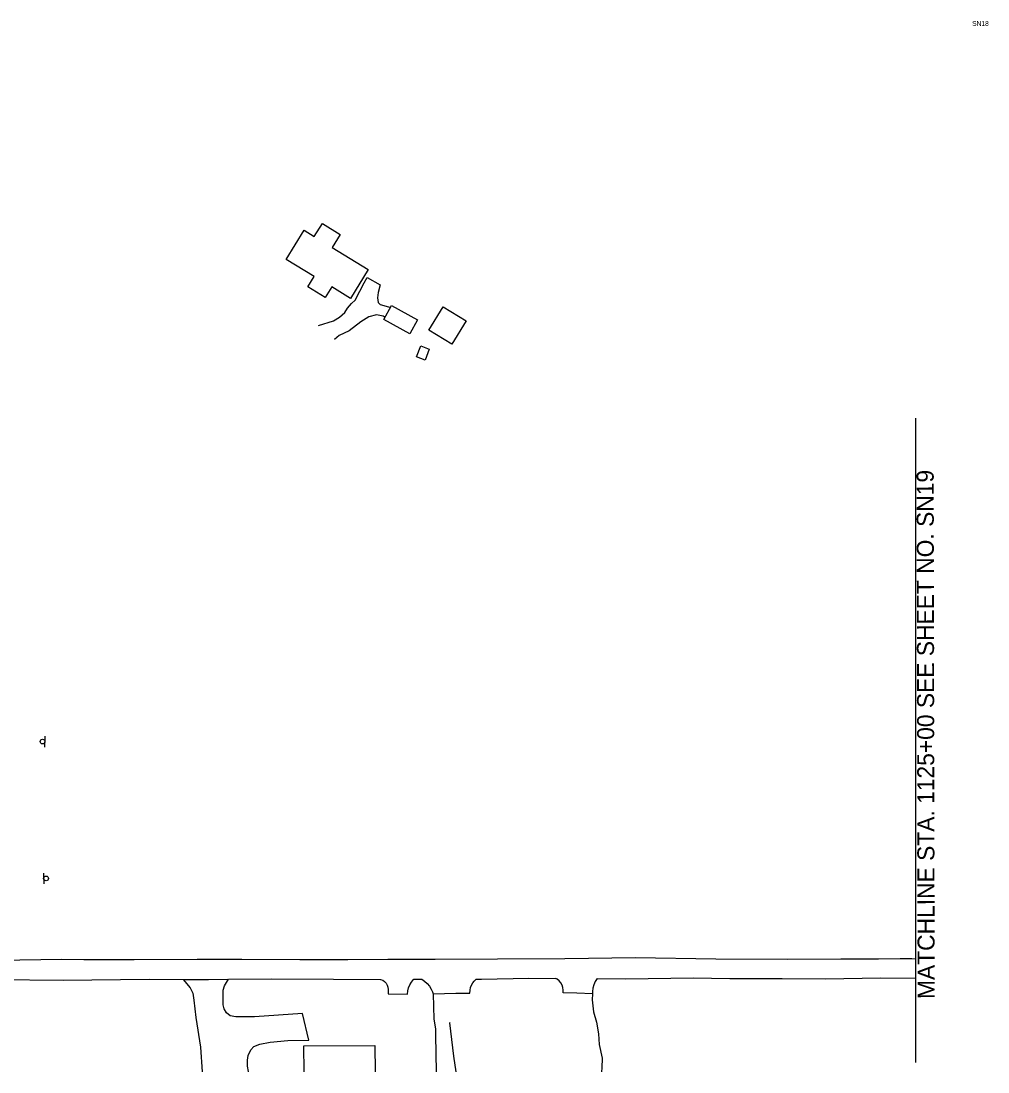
# Model space of a CAD drawing. Extents: x 1738714 to 1740304, y 1169218 to 1170094.
# Drawn here: x 1739500 to 1740304, y 1169221 to 1170094 of the extents above; entities that cross this region are included whole.
import ezdxf

# ---------------------------------------------------------------- set-up
doc = ezdxf.new("R2010")
doc.units = 0
for name, color, linetype in [('RD_EX_Bldg', 7, 'Continuous'), ('RD_EX_Driveway', 7, 'Continuous'), ('RD_EX_Road', 7, 'Continuous'), ('RD_SHT_MatchLine', 7, 'Continuous'), ('RD_SHT_TX', 7, 'Continuous'), ('SN_P_Signs', 7, 'Continuous')]:
    doc.layers.add(name, color=color, linetype=linetype)

msp = doc.modelspace()

# ---------------------------------------------------------------- linework, layer by layer
at = {"layer": 'RD_EX_Bldg'}
for points in [[(1739750.66, 1169926.27), (1739765.51, 1169917.12), (1739758.84, 1169906.29), (1739788.79, 1169887.84), (1739774.1, 1169863.99), (1739758.53, 1169873.58), (1739753.01, 1169864.63), (1739738.49, 1169873.57), (1739743.75, 1169882.11), (1739720.68, 1169896.33), (1739735.58, 1169920.52), (1739743.95, 1169915.37), (1739750.66, 1169926.27)], [(1739823.35, 1169834.54), (1739801.75, 1169846.4), (1739808.11, 1169857.99), (1739829.71, 1169846.12), (1739823.35, 1169834.54)], [(1739858.26, 1169825.88), (1739839.14, 1169837.5), (1739851, 1169857.02), (1739870.12, 1169845.41), (1739858.26, 1169825.88)], [(1739839.51, 1169821.81), (1739836.06, 1169812.69), (1739828.88, 1169815.41), (1739832.34, 1169824.53), (1739839.51, 1169821.81)], [(1739735.42, 1169221.05), (1739735.26, 1169242.76), (1739794.26, 1169243.18), (1739794.41, 1169221.05)]]:
    msp.add_lwpolyline(points, dxfattribs=at)
at = {"layer": 'RD_EX_Driveway'}
for points in [[(1739747.41, 1169841.34), (1739759.75, 1169845.31), (1739764.84, 1169848.33), (1739769.37, 1169852.34), (1739771.6, 1169855.81), (1739774.93, 1169859.68), (1739778.02, 1169862.53), (1739781.86, 1169869.92), (1739785.25, 1169876.84), (1739787.84, 1169881.19), (1739798.72, 1169875.26), (1739797.1, 1169868.81), (1739796.5, 1169864.51), (1739797.12, 1169860.48), (1739798.8, 1169858.84), (1739805.46, 1169856.8), (1739807.35, 1169856.6)], [(1739802.68, 1169848.1), (1739801.06, 1169849.08), (1739795.62, 1169850.19), (1739789.23, 1169848.63), (1739782.71, 1169844.57), (1739772.9, 1169837.03), (1739764.66, 1169833.02), (1739760.61, 1169829.75)]]:
    msp.add_lwpolyline(points, dxfattribs=at)
at = {"layer": 'RD_EX_Road'}
msp.add_line((1739826.61, 1169298.1), (1739833.17, 1169298.12), dxfattribs=at)
for points in [[(1740243.73, 1169314.93), (1740240.32, 1169315.05), (1740230.62, 1169315), (1740212.67, 1169314.94), (1740181.53, 1169314.73), (1740137.16, 1169314.62), (1740077.63, 1169314.73), (1740010.76, 1169315.92), (1739952.23, 1169314.97), (1739896.13, 1169314.93), (1739844.4, 1169314.63), (1739805.05, 1169314.44), (1739771.76, 1169314.18), (1739731.89, 1169314.16), (1739683.71, 1169314.5), (1739646.61, 1169314.48), (1739594.13, 1169314.19), (1739552.33, 1169314.28), (1739534.1, 1169314.5), (1739481.65, 1169313.81)], [(1739479.38, 1169297.87), (1739535.2, 1169297.4), (1739606.83, 1169298.12), (1739634.9, 1169298.03), (1739655.99, 1169297.97), (1739672.67, 1169298.1), (1739708.35, 1169298.39), (1739759.99, 1169298.21), (1739799.02, 1169298)], [(1739634.9, 1169298.03), (1739640.77, 1169290.9), (1739642.96, 1169286.53), (1739643.82, 1169280.84), (1739645.44, 1169266.26), (1739649.32, 1169241.55), (1739650.77, 1169221.05)], [(1739689.23, 1169221.05), (1739689.13, 1169221.36), (1739688.55, 1169225.95), (1739688.54, 1169230.76), (1739688.85, 1169234.86), (1739691.09, 1169239.55), (1739693.79, 1169242.32), (1739698.65, 1169244.2), (1739707.35, 1169245.79), (1739722, 1169247.15), (1739739.32, 1169247.55), (1739734.26, 1169269.6), (1739694.2, 1169266.86), (1739678.61, 1169266.8), (1739673.93, 1169267.84), (1739671.11, 1169270.14), (1739669.08, 1169273.56), (1739668.25, 1169276.98), (1739668.16, 1169281.12), (1739668.09, 1169289.11), (1739669.28, 1169292.71), (1739672.67, 1169298.1)], [(1739799.02, 1169298), (1739800.81, 1169297.23), (1739802.34, 1169296.16), (1739803.6, 1169294.78), (1739804.55, 1169293.17), (1739805.14, 1169291.4), (1739805.34, 1169289.55), (1739805.24, 1169288.2), (1739805.19, 1169285.89), (1739821.29, 1169285.75), (1739821.56, 1169288.41), (1739822.23, 1169291.01), (1739823.27, 1169293.49), (1739824.66, 1169295.78), (1739826.37, 1169297.85), (1739826.61, 1169298.1)], [(1739833.17, 1169298.12), (1739835.4, 1169296.59), (1739837.62, 1169294.59), (1739839.55, 1169292.31), (1739841.17, 1169289.79), (1739842.21, 1169287.66), (1739842.68, 1169285.9), (1739861.41, 1169286.65), (1739873.27, 1169286.63), (1739873.32, 1169288.91), (1739873.77, 1169291.14), (1739874.59, 1169293.26), (1739875.77, 1169295.2), (1739876.76, 1169296.4), (1739877.58, 1169297.36), (1739878.39, 1169298.3)], [(1739878.39, 1169298.3), (1739882.89, 1169298.31), (1739922.09, 1169298.88), (1739944.75, 1169298.84)], [(1739978.88, 1169298.65), (1739977.4, 1169296.19), (1739976.26, 1169293.54), (1739975.49, 1169290.76), (1739975.11, 1169287.91), (1739975.07, 1169285.93), (1739962.14, 1169286.41), (1739950.64, 1169286.84), (1739950.74, 1169289), (1739950.46, 1169291.14), (1739949.79, 1169293.2), (1739948.76, 1169295.1), (1739947.4, 1169296.78), (1739945.76, 1169298.19), (1739944.75, 1169298.84)], [(1739978.88, 1169298.65), (1740002.84, 1169298.5), (1740058.8, 1169299.19), (1740089.28, 1169298.77), (1740132.83, 1169298.87), (1740168.37, 1169298.48), (1740214.77, 1169299.19), (1740243.73, 1169298.93)], [(1739842.68, 1169285.9), (1739843.33, 1169265), (1739844.55, 1169256.83), (1739844.72, 1169251.66), (1739845.22, 1169221.05)], [(1739975.07, 1169285.93), (1739974.82, 1169280.97), (1739975.87, 1169271.07), (1739978.34, 1169262.37), (1739980.07, 1169252.68), (1739980.69, 1169243.86), (1739983.2, 1169232.4), (1739982.97, 1169224.56), (1739982.7, 1169221.05)], [(1739861.72, 1169221.05), (1739860.01, 1169234.06), (1739856.65, 1169261.84), (1739856.91, 1169262.3)]]:
    msp.add_lwpolyline(points, dxfattribs=at)
at = {"layer": 'RD_SHT_MatchLine'}
msp.add_lwpolyline([(1740243.73, 1169228.9), (1740243.73, 1169403.9), (1740243.73, 1169764.45)], dxfattribs=at)
at = {"layer": 'SN_P_Signs'}
for p, q in [((1739520.11, 1169491.09), (1739520.22, 1169500.09)), ((1739518.96, 1169386.38), (1739519.08, 1169377.38))]:
    msp.add_line(p, q, dxfattribs=at)
for centre in [(1739518.14, 1169495.63), (1739521.05, 1169381.89)]:
    msp.add_circle(centre, 2, dxfattribs=at)

# ---------------------------------------------------------------- texts
at = {"layer": 'RD_SHT_TX'}
msp.add_text('SN18', height=4, dxfattribs=at).set_placement((1740290.57, 1170090.4))
msp.add_text('MATCHLINE STA. 1125+00 SEE SHEET NO. SN19', height=14.1726, rotation=90.11236, dxfattribs=at).set_placement((1740259.45, 1169281.69))

doc.saveas('drawing.dxf')
